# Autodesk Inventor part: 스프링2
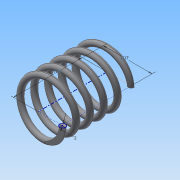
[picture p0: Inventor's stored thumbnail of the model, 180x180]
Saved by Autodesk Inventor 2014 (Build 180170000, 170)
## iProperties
Created: 2016-01
Part Number: 스프링2
Material: 강철, 탄소
Document SubType Name: Modeling
Designer: Administrator
Density: 1 g/cm^3
Appearance: 반연마
Mass: 0.819704 g
Surface Area: 16.7052 cm^2
Volume: 0.819704 cm^3
Author: Administrator
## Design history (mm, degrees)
sketch "스케치1"
  geometry: L1 (0, 0)-(8.5, 0); L2 (8.5, 0)-(8.5, 17.5); L3 (8.5, 17.5)-(0, 17.5); L4 (0, 17.5)-(0, 0); C1 r 1 at (8.5, 0)
  constraints: 8 end point, 2 parallel, 1 centre point, 1 coincident, 1 horizontal, 1 perpendicular
  dimensions: "d0" = 17.5 distance of L3.end L1.start (derived); "d1" = 17 diameter of L2 L4; "d2" = 2 diameter of C1
feature "코일1" pitch "d3" = 10; turns "d5" = 5; dims "d4" = 17.5 (= d0), "d6" = 0, angle "d7" = 90 deg, angle "d8" = 90 deg, "d9" = 0, "d10" = 0
node "작업 평면1"
sketch "스케치2"
  geometry: L1 (7.5, 0)-(9.5, 0) reference; 1 further point
  constraints: 1 horizontal alignment
extrude "돌출1" cut sketch "스케치2" stored distance "d12" = 10; taper "d13" = 0 deg
node "작업 평면2"
sketch "스케치3"
  geometry: L1 (-7.5, 0)-(-9.5, 0) reference; 1 further point
  constraints: 1 horizontal alignment
extrude "돌출2" cut sketch "스케치3" stored distance "d15" = 10; taper "d16" = 0 deg
node "솔리드1"
node "절단 모서리 투영1"
node "절단 모서리 투영2"
other parameters: "d11" = 0, "d14" = 17.5 (= d0)
